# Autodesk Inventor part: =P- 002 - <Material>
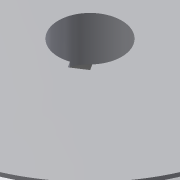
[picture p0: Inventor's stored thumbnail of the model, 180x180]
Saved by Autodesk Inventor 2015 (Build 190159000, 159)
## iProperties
Created: 2007-02
Part Number: =P- 002 - <Material>
Material: Aluminum-6061
Document SubType Name: Modeling
Designer: Autodesk, Inc.
Density: 2.71 g/cm^3
Mass: 4993.17 g
Surface Area: 1777.28 cm^2
Volume: 1842.5 cm^3
Description: =Pulley - <Mass>
Appearance: Aluminum - Flat
CustomPartVersion: 1
Author: Autodesk, Inc.
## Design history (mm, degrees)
sketch "Main Sketch"
  geometry: L1 (0, 34.925)-(137.795, 34.925); L2 (137.795, 34.925)-(137.795, 15.927); L3 (137.795, 15.927)-(126.111, 11.904); L4 (126.111, 11.904)-(126.111, 7.146); L5 (126.111, 7.146)-(137.795, 3.123); L6 (137.795, 3.123)-(137.795, 0); L7 (137.795, 0)-(0, 0); L8 (134.62, 14.834)-(134.62, 4.216); L9 (0, 34.925)-(0, 0); L10 (126.111, 9.525)-(134.62, 9.525); L11 (137.795, 15.927)-(137.795, 3.123); L12 (0, -6.985)-(0, 41.91) reference
  constraints: 22 end point, 5 perpendicular, 3 collinear, 2 midpoint, 2 point on line, 1 parallel
  dimensions: "d0" = 10.6172 distance of L8.start L8.end (= da_Bw); "d1" = 38 deg angle of L3 L5 (= da_Alfa); "d2" = 3.175 distance between parallel lines of L2 L8 (= da_c); "d6" = 34.925 distance between parallel lines of L7 L1 (computed from d5, da_ng, da_Sg); "d21" = 269.24 diameter of L8 L12 (= da_Dw); "d25" = 11.684 distance between parallel lines of L4 L11 (= da_Hd); "d27" = 9.525 distance between parallel lines of L7 L10 (= da_Se)
node "Belt Plane"
revolve "Body" stored, may be unused: angle "d7" = 90 deg
revolve "Groove" stored, may be unused: angle "d15" = 90 deg
fillet "Fillet External" dims "d8" = 0 (computed from da_r1), "d10" = 0, "da_r1" = 0 [user parameter; used in 1 equation term]
fillet "Fillet Internal" dims "d9" = 0 (computed from da_r2), "d11" = 0, "da_r2" = 0 [user parameter; used in 1 equation term]
pattern_linear "Groove Pattern" dims "d18" = 15.875 (= da_Sg)
feature "Hub Keyway"
body "Solid1"
other parameters: "d5" = 9.525 (= da_Se), "da_Bw" = 10.6172 [user parameter; used in 1 equation term], "da_Alfa" = 38 deg [user parameter; used in 1 equation term], "da_c" = 3.175 [user parameter; used in 1 equation term], "da_Dw" = 269.24 [user parameter; used in 1 equation term], "da_Hd" = 11.684 [user parameter; used in 1 equation term], "da_Se" = 9.525 [user parameter; used in 2 equation terms], "da_Sg" = 15.875 [user parameter; used in 2 equation terms], "d24" = 0, "d26" = 0
